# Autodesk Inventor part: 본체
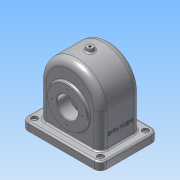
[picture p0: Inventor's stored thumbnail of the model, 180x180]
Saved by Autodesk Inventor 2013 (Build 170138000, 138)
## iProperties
Created: 2016-10
Part Number: 본체
Material: 알루미늄 6061
Document SubType Name: Modeling
Designer: Administrator
Density: 2.71 g/cm^3
Mass: 1169.47 g
Surface Area: 1209.37 cm^2
Volume: 431.537 cm^3
Author: Administrator
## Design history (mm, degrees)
sketch "스케치1"
  geometry: L1 (-75, 55)-(75, 55); L2 (75, 55)-(75, -55); L3 (75, -55)-(-75, -55); L4 (-75, -55)-(-75, 55); 3 further points
  constraints: 8 end point, 2 midpoint, 2 parallel, 1 horizontal, 1 horizontal alignment, 1 perpendicular, 1 vertical alignment
  dimensions: "d0" = 150 distance of L2.end L3.end; "d1" = 110 distance of L1.end L2.end
extrude "돌출1" new body sketch "스케치1" distance "d2" = 15; taper "d3" = 0 deg
sketch "스케치2"
  geometry: L1 (-75, 0)-(75, 0) reference; L2 (-58, 0)-(-58, 80); L3 (58, 80)-(58, 0); A1 r 58 centre (0, 80) between (58, 80) and (-58, 80); 2 further points
  constraints: 4 end point, 2 perpendicular, 2 point on circle, 2 point on line, 2 tangent, 1 centre point, 1 midpoint, 1 vertical alignment
  dimensions: "d4" = 80 distance from line of L1 A1.centre; "d5" = 58 radius of A1
extrude "돌출2" join sketch "스케치2" stored distance "d6" = 77; taper "d7" = 0 deg
sketch "스케치3"
  geometry: L1 (-58, 15)-(-58, 80) reference; L2 (58, 80)-(58, 15) reference; L3 (-52, 0)-(-52, 80); L4 (52, 80)-(52, 0); L5 (-75, 0)-(75, 0) reference; A1 r 58 centre (0, 80) between (58, 80) and (-58, 80) reference; A2 r 52 centre (0, 80) between (52, 80) and (-52, 80); 1 further point
  constraints: 4 end point, 2 point on circle, 2 point on line, 1 centre point, 2 other
  dimensions: "d8" = 6 radial gap between concentric circles of A1 A2
extrude "돌출3" cut sketch "스케치3" stored distance "d9" = 67; taper "d10" = 0 deg
node "작업 평면1"
sketch "스케치4"
  geometry: C1 r 6 at (0, 0); 1 further point
  constraints: 1 centre point, 1 coincident
  dimensions: "d12" = 12 diameter of C1
extrude "돌출4" join sketch "스케치4" distance "d13" = 10; taper "d14" = 10 deg
sketch "스케치5"
  geometry: L1 (-75, 0)-(75, 0) reference; C1 r 31 at (0, -65); 2 further points
  constraints: 1 centre point, 1 midpoint, 1 vertical alignment
  dimensions: "d15" = 62 diameter of C1; "d16" = 65 distance from line of L1 C1.centre
extrude "돌출5" join sketch "스케치5" distance "d17" = 10; taper "d18" = 0 deg
sketch "스케치6"
  geometry: L1 (-38.5, 80)-(-38.5, 15) reference; L2 (-33.5, 132)-(-33.5, 80) reference; L3 (-38.5, 138)-(-38.5, 80) reference; L4 (-43.5, 65)-(-19.5, 65); L5 (33.5, 0)-(-33.5, 0) reference; L6 (-19.5, 65)-(-19.5, 93); L7 (-19.5, 93)-(-38.5, 108.943); L8 (-43.5, 65)-(-43.5, 102.5); L9 (-43.5, 102.5)-(-38.5, 102.5); L10 (-38.5, 108.943)-(-38.5, 102.5); 1 further point
  constraints: 12 end point, 3 perpendicular, 2 point on line, 1 collinear, 1 parallel
  dimensions: "d19" = 24 distance of L4.start L4.end; "d21" = 65 distance between parallel lines of L5 L4; "d22" = 5 distance from line of L1 L4.start; "d23" = 56 diameter of L6.end L4; "d24" = 50 deg angle of L6 L7; "d26" = 75 diameter of L9 L4
revolve "회전1" sketch "스케치6" stored, may be unused: angle "d27" = 90 deg
hole "구멍1" diameter "d30" = 40; stored, may be unused: countersink angle "d34" = 90 deg, drill point angle "d36" = 118 deg; dims "d28" = 10, "d29" = 10, "d31" = 6, "d32" = 4, "d33" = 2, "d35" = 8
sketch "스케치7"
  geometry: C1 r 37.5 at (0, 0) reference; A1 r 29 centre (0, 0) between (0, 29) and (-29, 0); 3 further points
  constraints: 4 point on circle, 2 horizontal alignment, 2 vertical alignment, 1 centre point, 1 coincident
  dimensions: "d37" = 58 diameter of A1
hole "구멍2" sketch "스케치7" at (0, 29), (-29, 0), (0, -29), (29, 0) diameter "d38" = 2.459; stored, may be unused: countersink angle "d42" = 90 deg, drill point angle "d44" = 118 deg; dims "d39" = 6, "d40" = 4, "d41" = 2, "d43" = 8
sketch "스케치8"
  geometry: C1 r 31 at (0, 0) reference; A1 r 26 centre (0, 0) between (0, -26) and (26, 0); 3 further points
  constraints: 4 point on circle, 2 horizontal alignment, 2 vertical alignment, 1 centre point, 1 coincident
  dimensions: "d45" = 52 diameter of A1
hole "구멍3" sketch "스케치8" at (0, -26), (26, 0), (0, 26), (-26, 0) diameter "d46" = 2.459; stored, may be unused: countersink angle "d50" = 90 deg, drill point angle "d52" = 118 deg; dims "d47" = 6, "d48" = 4, "d49" = 2, "d51" = 8
hole "구멍4" diameter "d55" = 4.459; stored, may be unused: countersink angle "d59" = 90 deg, drill point angle "d61" = 118 deg; dims "d53" = 10, "d54" = 10, "d56" = 30, "d57" = 4, "d58" = 2, "d60" = 8
sketch "스케치9"
  geometry: L1 (15, 93.5)-(15, -16.5) reference; L2 (0, 0)-(-65, 0) reference; 2 further points
  constraints: 1 other
  dimensions: "d62" = 40 distance from line of L1 point (-25, 38.5); "d63" = 38.5 distance from line of point (-25, 38.5) L2
feature "엠보싱1" sketch "스케치9" dims "d0" = 150, "d1" = 110, "d64" = 0.5, "d65" = 0
fillet "모깎기1" dims "d66" = 13
fillet "모깎기2" dims "d67" = 8
fillet "모깎기3" dims "d68" = 12
hole "구멍5" diameter "d71" = 5; stored, may be unused: countersink angle "d75" = 90 deg, drill point angle "d77" = 118 deg; dims "d69" = 10, "d70" = 10, "d72" = 30, "d73" = 12, "d74" = 5, "d76" = 8
hole "구멍6" diameter "d80" = 5; stored, may be unused: countersink angle "d84" = 90 deg, drill point angle "d86" = 118 deg; dims "d78" = 10, "d79" = 10, "d81" = 30, "d82" = 12, "d83" = 5, "d85" = 8
hole "구멍7" diameter "d89" = 5; stored, may be unused: countersink angle "d93" = 90 deg, drill point angle "d95" = 118 deg; dims "d87" = 10, "d88" = 10, "d90" = 30, "d91" = 12, "d92" = 5, "d94" = 8
hole "구멍8" diameter "d98" = 5; stored, may be unused: countersink angle "d102" = 90 deg, drill point angle "d104" = 118 deg; dims "d96" = 10, "d97" = 10, "d99" = 30, "d100" = 12, "d101" = 5, "d103" = 8
chamfer "모따기1" distance "d105" = 1; stored, may be unused: second distance "d106" = 2, angle "d107" = 45 deg
fillet "모깎기4" dims "d108" = 3
node "솔리드1"
other parameters: "d11" = 144
